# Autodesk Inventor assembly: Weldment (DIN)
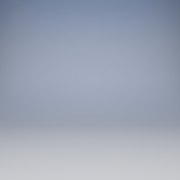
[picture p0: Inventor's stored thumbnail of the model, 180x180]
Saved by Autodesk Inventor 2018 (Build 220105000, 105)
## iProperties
Created: 2017-02
Part Number: Weldment (DIN)
Material: Ogólny
Document SubType Name: Weldment
Weld Material: Welded Aluminum-6061
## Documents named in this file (1)
- C:\Users\Joffi\Desktop\Templates.Base\Metric.Base\Weldment (DIN).iam
